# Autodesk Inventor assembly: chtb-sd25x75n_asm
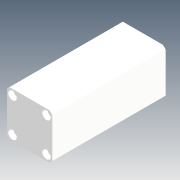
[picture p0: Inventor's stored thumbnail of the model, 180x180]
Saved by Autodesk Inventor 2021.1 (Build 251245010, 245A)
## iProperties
Company: Microsoft
Created: 2018-05
Part Number: chtb-sd25x75n_asm
Description: STEP AP214
Document SubType Name: Assembly
Designer: user
Title: chtb-sd25x75n_asm.STEP
Author: Windows
Revision Number: ÈÎºÎ
Sending System: SolidWorks 2015
Preprocessor: SwSTEP 2.0
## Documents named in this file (4)
- D:\Vault_2016\Projekty\Clamptek\Hydraulic\CHTB\CHTB-25\Inventor\chtb-sd25x75n\chtb-sd25x75n_asm.iam
- D:\Vault_2016\Projekty\Clamptek\Hydraulic\CHTB\CHTB-25\Inventor\chtb-sd25x75n\CHTB-25QG.ipt
- D:\Vault_2016\Projekty\Clamptek\Hydraulic\CHTB\CHTB-25\Inventor\chtb-sd25x75n\CHTB-SD25X75NBT.ipt
- D:\Vault_2016\Projekty\Clamptek\Hydraulic\CHTB\CHTB-25\Inventor\chtb-sd25x75n\CHTB-SD25X75NHSG.ipt
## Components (3 placed, 3 different names)
1. CHTB-25QG_1
2. CHTB-SD25X75NBT_2
3. CHTB-SD25X75NHSG_3
